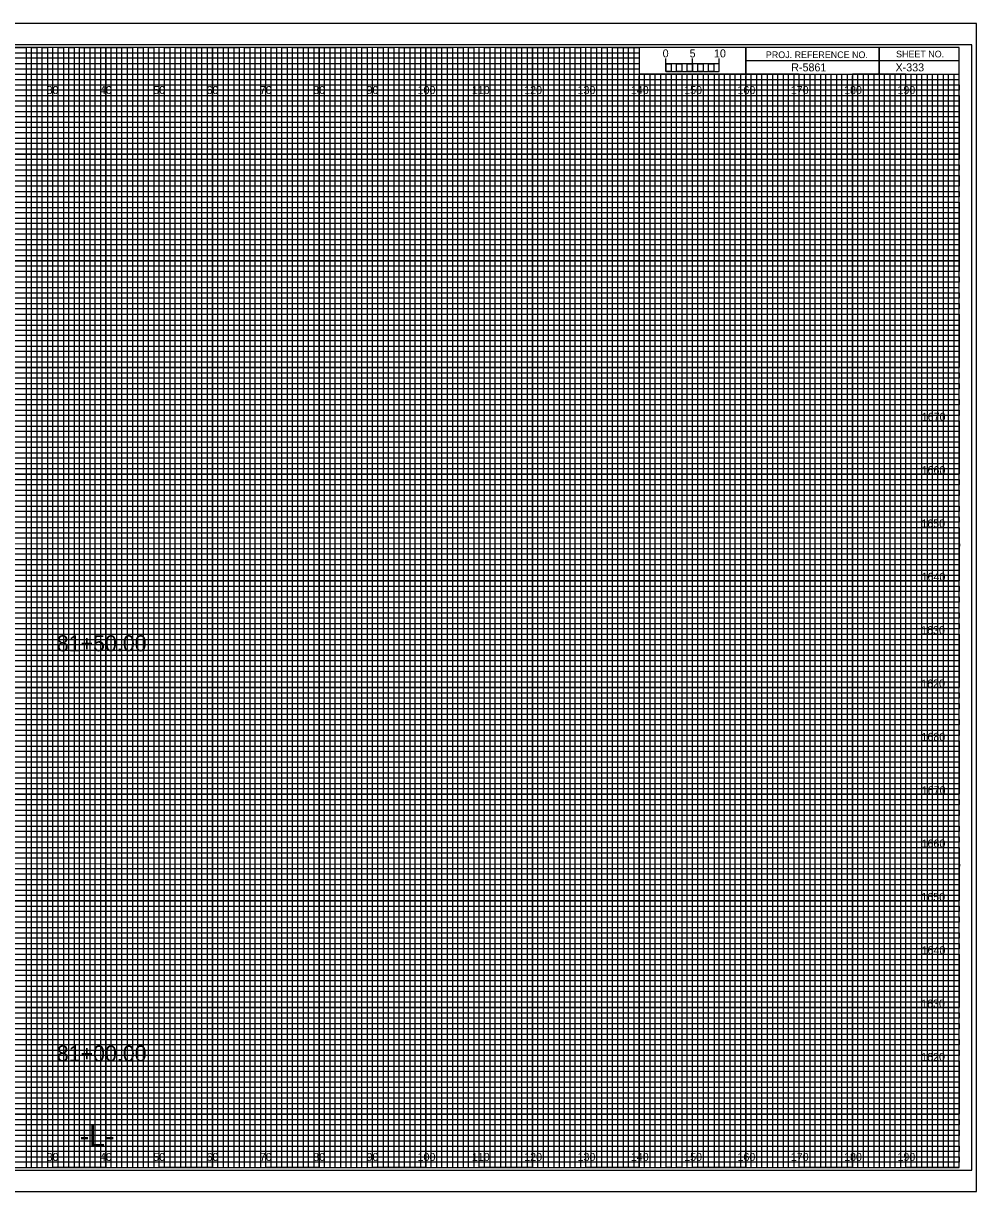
# Model space of a CAD drawing. Extents: x -13 to 1780, y -15 to 3284.
# Drawn here: x 144.5 to 323.3, y 215.5 to 434.5 of the extents above; entities that cross this region are included whole.
import ezdxf

# ---------------------------------------------------------------- set-up
doc = ezdxf.new("R2010")
doc.units = 0
for name, color, linetype in [('Exist CMT Pavement', 7, 'Continuous'), ('Prop Horizontal Alignment', 7, 'Continuous'), ('Prop Retaining Wall', 7, 'Continuous'), ('Prop SS Cut Line', 7, 'Continuous'), ('Prop SS Fill Line', 7, 'Continuous'), ('Prop SS Transition Line', 7, 'Continuous'), ('Prop XS Bar Scale Labels', 7, 'Continuous'), ('Prop XS DDE', 7, 'Continuous'), ('Prop XS Earthwork Shape', 7, 'Continuous'), ('Prop XS Noise Wall', 7, 'Continuous'), ('Prop XS Retaining Wall', 7, 'Continuous'), ('Prop XS Station Labels', 7, 'Continuous'), ('Raster_Level_0', 7, 'Continuous'), ('Scratch_Level_3', 7, 'Continuous'), ('Scratch_Level_7', 7, 'Continuous'), ('Typical Bridge Rail CELL', 7, 'Continuous'), ('Typical Median Barrier CELL', 7, 'Continuous')]:
    doc.layers.add(name, color=color, linetype=linetype)

msp = doc.modelspace()

# ---------------------------------------------------------------- linework, layer by layer
at = {"layer": 'Prop Retaining Wall'}
for p, q in [((305, 430), (305, 425)), ((305, 425), (305, 430)), ((280, 427.5), (280, 425)), ((320, 427.49), (280, 427.49)), ((280, 425), (320, 425))]:
    msp.add_line(p, q, dxfattribs=at)
for points in [[(320, 430), (0, 430), (0, 220), (320, 220)], [(280, 430), (260, 430), (260, 425.03), (280, 425.03)], [(320, 430), (280, 430), (280, 425), (320, 425)]]:
    msp.add_lwpolyline(points, close=True, dxfattribs=at)
at = {"layer": 'Prop SS Cut Line'}
for points in [[(135, 430), (145, 430), (145, 220), (155, 220), (155, 430), (165, 430), (165, 220), (175, 220), (175, 430), (185, 430), (185, 220), (195, 220), (195, 430), (205, 430), (205, 220), (215, 220), (215, 430), (225, 430), (225, 220), (235, 220), (235, 430), (245, 430), (245, 220), (255, 220), (255, 430), (259.93, 430), (260, 430), (260, 425), (264.99, 425), (264.99, 220), (275, 220), (275, 425), (285, 425), (285, 220), (295, 220), (295, 425), (305, 425), (305, 220), (315, 220), (315, 425)], [(0, 425), (275, 425)], [(0, 405), (320, 405), (320, 415), (0, 415)], [(0, 385), (320, 385), (320, 395), (0, 395)], [(0, 365), (320, 365), (320, 375), (0, 375)], [(0, 345), (320, 345), (320, 355), (0, 355)], [(0, 325), (320, 325), (320, 335), (0, 335)], [(0, 305), (320, 305), (320, 315), (0, 315)], [(0, 285), (320, 285), (320, 295), (0, 295)], [(0, 265), (320, 265), (320, 275), (0, 275)], [(0, 245), (320, 245), (320, 255), (0, 255)], [(0, 225), (320, 225), (320, 235), (0, 235)]]:
    msp.add_lwpolyline(points, dxfattribs=at)
at = {"layer": 'Prop SS Fill Line'}
for p, q in [((150, 430), (140, 430)), ((150, 220), (150, 430)), ((170, 430), (160, 430)), ((160, 430), (160, 220)), ((170, 220), (170, 430)), ((190, 430), (180, 430)), ((180, 430), (180, 220)), ((190, 220), (190, 430)), ((210, 430), (200, 430)), ((200, 430), (200, 220)), ((210, 220), (210, 430)), ((230, 430), (220, 430)), ((220, 430), (220, 220)), ((230, 220), (230, 430)), ((250, 430), (240, 430)), ((240, 430), (240, 220)), ((250, 220), (250, 430)), ((260, 430), (260, 220)), ((270, 220), (270, 425)), ((290, 425), (280, 425)), ((280, 425), (280, 220)), ((290, 220), (290, 425)), ((310, 425), (300, 425)), ((300, 425), (300, 220)), ((310, 220), (310, 425)), ((160, 220), (150, 220)), ((180, 220), (170, 220)), ((200, 220), (190, 220)), ((220, 220), (210, 220)), ((240, 220), (230, 220)), ((260, 220), (250, 220)), ((280, 220), (270, 220)), ((300, 220), (290, 220)), ((320, 220), (310, 220)), ((320, 220), (320, 220))]:
    msp.add_line(p, q, dxfattribs=at)
for points in [[(0, 420), (320, 420), (320, 410), (0, 410)], [(0, 400), (320, 400), (320, 390), (0, 390)], [(0, 380), (320, 380), (320, 370), (0, 370)], [(0, 360), (320, 360), (320, 350), (0, 350)], [(0, 340), (320, 340), (320, 330), (0, 330)], [(0, 320), (320, 320), (320, 310), (0, 310)], [(0, 300), (320, 300), (320, 290), (0, 290)], [(0, 280), (320, 280), (320, 270), (0, 270)], [(0, 260), (320, 260), (320, 250), (0, 250)], [(0, 240), (320, 240), (320, 230), (0, 230)]]:
    msp.add_lwpolyline(points, dxfattribs=at)
at = {"layer": 'Prop SS Transition Line'}
for p, q in [((0, 429), (260, 429)), ((260, 427.98), (0, 427.98)), ((260, 429), (260, 427.98)), ((0, 427), (260, 427)), ((260, 425.89), (0, 425.89)), ((260, 427), (260, 425.89)), ((0, 424), (320, 424))]:
    msp.add_line(p, q, dxfattribs=at)
for points in [[(0, 423), (270, 423), (320, 423), (320, 422), (0, 422)], [(0, 421), (320, 421), (320, 419), (0, 419)], [(0, 418), (320, 418), (320, 417), (0, 416.98)], [(0, 416), (320, 416), (320, 414), (0, 414)], [(0, 413), (320, 413), (320, 412), (0, 412)], [(0, 411), (320, 411), (320, 409), (0, 409)], [(0, 408), (320, 408), (320, 407), (0, 407)], [(0, 406), (320, 406), (320, 404), (0, 404)], [(0, 403), (320, 403), (320, 402), (0, 402)], [(0, 401), (320, 401), (320, 399), (0, 399)], [(0, 398), (320, 398), (320, 397), (0, 397)], [(0, 396), (320, 396), (320, 393.95), (320, 393), (320, 392), (0, 392)], [(0, 394), (320, 394), (320, 393), (0, 393)], [(0, 391), (320, 391), (320, 389), (0, 389.03)], [(0, 389.03), (320, 389), (320, 388), (0, 388)], [(0, 387), (320, 387), (320, 386), (0, 386)], [(0, 384), (320, 384), (320, 383), (0, 383)], [(0, 382), (320, 382), (320, 381), (0, 381)], [(-0.07, 378.89), (320, 378.89), (320, 377.88), (-0.07, 377.88)], [(0, 377), (320, 377), (320, 376), (0, 376)], [(0, 374), (320, 374), (320, 373), (0, 373)], [(0, 372), (320, 372), (320, 371), (0, 371)], [(0, 369), (320, 369), (320, 368), (0, 368)], [(0, 367), (320, 367), (320, 366), (0, 366)], [(0, 364), (320, 364), (320, 363), (0, 363)], [(0, 362), (320, 362), (320, 361), (0, 361)], [(0, 359), (320, 359), (319.99, 357.98), (0, 358)], [(0, 357), (320, 357), (320, 356), (0, 356)], [(0, 354), (320, 354), (320, 353), (0, 353)], [(0, 352), (320, 352), (320, 351), (0, 351)], [(0, 349), (320, 349), (320, 348), (0, 348)], [(0, 347), (320, 347), (320, 346), (0, 346)], [(0, 344), (320, 344), (320, 343), (0, 343)], [(0, 342), (320, 342), (320, 341), (0, 341)], [(0, 339), (320, 339), (320, 338), (0, 338)], [(0, 336.99), (320.07, 336.91), (320, 336), (0, 336)], [(0, 334), (320, 334), (320, 333), (0, 333)], [(0, 332), (320, 332), (320, 331), (0, 331)], [(0, 329), (320, 329), (320, 328), (0, 328)], [(0, 327), (320, 327), (320, 326), (0, 326)], [(0, 324), (320, 324), (320, 323), (0, 323)], [(0, 322), (320, 322), (320, 321), (0, 321)], [(0, 319), (320, 319), (320, 318), (0, 318)], [(0, 317), (320, 317), (320, 316), (0, 316)], [(0, 314), (320, 314), (320, 313), (0, 313)], [(0, 312), (320, 312), (320, 311), (0, 311)], [(0, 309), (320, 309), (320, 308), (0, 308)], [(0, 307), (320, 307), (320, 306), (0, 306)], [(0, 304), (320, 304), (320, 303), (0, 303)], [(0, 302), (320, 302), (320, 301), (0, 301)], [(0, 299), (320, 299), (319.99, 297.98), (0, 298)], [(0, 297), (320, 297), (320, 296), (0, 296)], [(0, 294), (320, 294), (320, 293), (0, 293)], [(0, 292), (320, 292), (320, 291), (0, 291)], [(0, 289), (320, 289), (320, 288), (0, 288)], [(0, 287), (320, 287), (320, 286), (0, 286)], [(0, 284), (320, 284), (320, 283), (0, 283)], [(0, 282), (320, 282), (320, 281), (0, 281)], [(0, 279), (320, 279), (320, 278), (0, 278)], [(0, 276.99), (320.07, 276.91), (320, 276), (0, 276)], [(0, 274), (320, 274), (320, 273), (0, 273)], [(0, 272), (320, 272), (320, 271), (0, 271)], [(0, 269), (320, 269), (320, 268), (0, 268)], [(0, 267), (320, 267), (320, 266), (0, 266)], [(0, 264), (320, 264), (320, 263), (0, 263)], [(0, 262), (320, 262), (320, 261), (0, 261)], [(0, 259), (320, 259), (320, 258), (0, 258)], [(0, 257), (320, 257), (320, 256), (0, 256)], [(0, 254), (320, 254), (320, 253), (0, 253)], [(0, 252), (320, 252), (320, 251), (0, 251)], [(0, 249), (320, 249), (320, 248), (0, 248)], [(0, 247), (320, 247), (320, 246), (0, 246)], [(0, 244), (320, 244), (320, 243), (0, 243)], [(0, 242), (320, 242), (320, 241), (0, 241)], [(0, 239), (320, 239), (320, 238), (0, 238)], [(0, 237), (320, 237), (320, 236), (0, 236)], [(0, 234), (320, 234), (320, 233), (0, 233)], [(0, 232), (320, 232), (320, 231), (0, 231)], [(0, 229), (320, 229), (320, 228), (0, 228)], [(0, 227), (320, 227), (320, 226), (0, 226)], [(0, 224), (320, 224), (320, 223), (0, 223)], [(0, 222), (320, 222), (320, 221), (0, 221)]]:
    msp.add_lwpolyline(points, dxfattribs=at)
at = {"layer": 'Prop XS Earthwork Shape'}
msp.add_lwpolyline([(-13.4, 215.5), (323.3, 215.5), (323.3, 434.5), (-13.4, 434.5)], close=True, dxfattribs=at)
at = {"layer": 'Prop XS Noise Wall'}
for p, q in [((150, 220), (150, 430)), ((160, 220), (160, 430)), ((170, 220), (170, 430)), ((180, 220), (180, 430)), ((190, 220), (190, 430)), ((200, 220), (200, 430)), ((210, 220), (210, 430)), ((220, 220), (220, 430)), ((230, 220), (230, 430)), ((240, 220), (240, 430)), ((250, 220), (250, 430)), ((260, 220), (260, 424.69)), ((270, 220), (270, 424.69)), ((280, 220), (280, 424.69)), ((290, 220), (290, 424.69)), ((300, 220), (300, 424.69)), ((310, 220), (310, 424.69)), ((0, 420), (320, 420)), ((0, 410), (320, 410)), ((0, 400), (320, 400)), ((0, 390), (320, 390)), ((0, 380), (320, 380)), ((0, 370), (320, 370)), ((0, 360), (320, 360)), ((0, 350), (320, 350)), ((0, 340), (320, 340)), ((0, 330), (320, 330)), ((0, 320), (320, 320)), ((0, 310), (320, 310)), ((0, 300), (320, 300)), ((0, 290), (320, 290)), ((0, 280), (320, 280)), ((0, 270), (320, 270)), ((0, 260), (320, 260)), ((0, 250), (320, 250)), ((0, 240), (320, 240)), ((0, 230), (320, 230))]:
    msp.add_line(p, q, dxfattribs=at)
at = {"layer": 'Prop XS Retaining Wall'}
for p, q in [((265, 425.49), (265, 427.9)), ((265, 426.9), (265, 427.9)), ((270, 425.49), (270, 427.9)), ((275, 425.49), (275, 427.9)), ((275, 426.9), (275, 427.9))]:
    msp.add_line(p, q, dxfattribs=at)
for points in [[(275, 426.9), (265, 426.9), (265, 425.49), (275, 425.49)], [(265, 426.9), (266, 426.9), (266, 425.49), (265, 425.49)], [(267, 426.9), (268, 426.9), (268, 425.49), (267, 425.49)], [(269, 426.9), (270, 426.9), (270, 425.49), (269, 425.49)], [(271, 426.9), (272, 426.9), (272, 425.49), (271, 425.49)], [(273, 426.9), (274, 426.9), (274, 425.49), (273, 425.49)]]:
    msp.add_lwpolyline(points, close=True, dxfattribs=at)
at = {"layer": 'Prop XS Station Labels'}
for p, q in [((323.3, 434.5), (-13.4, 434.5)), ((-13.4, 215.5), (323.3, 215.5))]:
    msp.add_line(p, q, dxfattribs=at)
at = {"layer": 'Scratch_Level_7'}
msp.add_lwpolyline([(-10.8, 219.5), (322.4, 219.5), (322.4, 430.5), (-10.8, 430.5)], close=True, dxfattribs=at)
at = {"layer": 'Typical Bridge Rail CELL'}
for p, q in [((267, 425), (266.01, 425)), ((266.01, 425), (266.01, 220)), ((267, 220), (267, 425)), ((269, 425), (268, 425)), ((268, 425), (268, 220)), ((269, 220), (269, 425)), ((266.01, 220), (265, 220)), ((268, 220), (267, 220))]:
    msp.add_line(p, q, dxfattribs=at)
for points in [[(145, 220), (146, 220), (146, 430), (147, 430), (147, 220)], [(147, 220), (148, 220), (148, 430), (149, 430), (149, 220)], [(150, 220), (151, 220), (151, 430), (152, 430), (152, 220)], [(152, 220), (153, 220), (153, 430), (154, 430), (154, 220)], [(155, 220), (156, 220), (156, 430), (157, 430), (157, 220)], [(157, 220), (158, 220), (158, 430), (159, 430), (159, 220)], [(160, 220), (161, 220), (161, 430), (162, 430), (162, 220)], [(162, 220), (163, 220), (163, 430), (164, 430), (164, 220)], [(165, 220), (166, 220), (166, 430), (167, 430), (167, 220)], [(167, 220), (168, 220), (168, 430), (169, 430), (169, 220)], [(170, 220), (171, 220), (171, 430), (172, 430), (172, 220)], [(172, 220), (173, 220), (173, 430), (174, 430), (174, 220)], [(175, 220), (176, 220), (176, 430), (177, 430), (177, 220)], [(177, 220), (178, 220), (178, 430), (179, 430), (179, 220)], [(180, 220), (181, 220), (181, 430), (182, 430), (182, 220)], [(182, 220), (183, 220), (183, 430), (184, 430), (184, 220)], [(185, 220), (186, 220), (186, 430), (187, 430), (187, 220)], [(187, 220), (188, 220), (188, 430), (189, 430), (189, 220)], [(190, 220), (191, 220), (191, 430), (192, 430), (192, 220)], [(192, 220), (193, 220), (193, 430), (194, 430), (194, 220)], [(195, 220), (196, 220), (196, 430), (197, 430), (197, 220)], [(197, 220), (198, 220), (198, 430), (199, 430), (199, 220)], [(200, 220), (201, 220), (201, 430), (202, 430), (202, 220)], [(202, 220), (203, 220), (203, 430), (204, 430), (204, 220)], [(205, 220), (206, 220), (206, 430), (207, 430), (207, 220)], [(207, 220), (208, 220), (208, 430), (209, 430), (209, 220)], [(210, 220), (211, 220), (211, 430), (212, 430), (212, 220)], [(212, 220), (213, 220), (213, 430), (214, 430), (214, 220)], [(215, 220), (216, 220), (216, 430), (217, 430), (217, 220)], [(217, 220), (218, 220), (218, 430), (219, 430), (219, 220)], [(220, 220), (221, 220), (221, 430), (222, 430), (222, 220)], [(222, 220), (223, 220), (223, 430), (224, 430), (224, 220)], [(225, 220), (226, 220), (226, 430), (227, 430), (227, 220)], [(227, 220), (228, 220), (228, 430), (229, 430), (229, 220)], [(230, 220), (231, 220), (231, 430), (232, 430), (232, 220)], [(232, 220), (233, 220), (233, 430), (234, 430), (234, 220)], [(235, 220), (236, 220), (236, 430), (237, 430), (237, 220)], [(237, 220), (238, 220), (238, 430), (239, 430), (239, 220)], [(240, 220), (241, 220), (241, 430), (242, 430), (242, 220)], [(242, 220), (243, 220), (243, 430), (244, 430), (244, 220)], [(245, 220), (246, 220), (246, 430), (247, 430), (247, 220)], [(247, 220), (248, 220), (248, 430), (249, 430), (249, 220)], [(250, 220), (251, 220), (251, 430), (252, 430), (252, 220)], [(252, 220), (253, 220), (253, 430), (254, 430), (254, 220)], [(255, 220), (256, 220), (256, 430), (257, 430), (257, 220)], [(257, 220), (258, 220), (258, 430), (259, 430), (259, 220)], [(260, 220), (261, 220), (261, 425), (262.02, 425), (262.02, 220)], [(262, 220), (263, 220), (263, 425), (263.99, 425), (263.99, 220)], [(270, 220), (270.98, 220), (270.98, 425), (272, 425), (272, 220)], [(272, 220), (273, 220), (273, 425), (274.05, 425), (274.05, 220)], [(275, 220), (276, 220), (276, 425), (277, 425), (277, 220)], [(277, 220), (278, 220), (278, 425), (279, 425), (279, 220)], [(280, 220), (281, 220), (281, 425), (282, 425), (282, 220)], [(282, 220), (283, 220), (283, 425), (284, 425), (284, 220)], [(285, 220), (286, 220), (286, 425), (287, 425), (287, 220)], [(287, 220), (288, 220), (288, 425), (289, 425), (289, 220)], [(290, 220), (291, 220), (291, 425), (292, 425), (292, 220)], [(292, 220), (293, 220), (293, 425), (294, 425), (294, 220)], [(295, 220), (296, 220), (296, 425), (297, 425), (297, 220)], [(297, 220), (298, 220), (298, 425), (299, 425), (299, 220)], [(300, 220), (301, 220), (301, 425), (302, 425), (302, 220)], [(302, 220), (303, 220), (303, 425), (304, 425), (304, 220)], [(305, 220), (306, 220), (306, 425), (307, 425), (307, 220)], [(307, 220), (308, 220), (308, 425), (309, 425), (309, 220)], [(310, 220), (311, 220), (311, 425), (312, 425), (312, 220)], [(312, 220), (313, 220), (313, 425), (314, 425), (314, 220)], [(315, 220), (316, 220), (316, 425), (317, 425), (317, 220)], [(317, 220), (318, 220), (318, 425), (319, 425), (319, 220)]]:
    msp.add_lwpolyline(points, dxfattribs=at)

# ---------------------------------------------------------------- texts
at = {"layer": 'Exist CMT Pavement'}
msp.add_text('R-5861', height=1.5, dxfattribs=at).set_placement((288.53, 425.5))
at = {"layer": 'Prop Horizontal Alignment'}
for s, p in [('81+50.00', (150.77, 316.79)), ('81+00.00', (150.77, 239.9))]:
    msp.add_text(s, height=3, dxfattribs=at).set_placement(p)
at = {"layer": 'Prop Retaining Wall'}
for s, p in [('PROJ. REFERENCE NO.', (283.77, 427.99)), ('SHEET NO.', (308.19, 428.12))]:
    msp.add_text(s, height=1.25, dxfattribs=at).set_placement(p)
at = {"layer": 'Prop XS Bar Scale Labels'}
for s, p in [('5', (269.47, 428.12)), ('10', (274.04, 428.12))]:
    msp.add_text(s, height=1.5, dxfattribs=at).set_placement(p)
at = {"layer": 'Prop XS DDE'}
msp.add_text('-L-', height=4, dxfattribs=at).set_placement((155.06, 224))
at = {"layer": 'Prop XS Retaining Wall'}
msp.add_text('0', height=1.5, dxfattribs=at).set_placement((264.41, 428.12))
at = {"layer": 'Raster_Level_0'}
for s, p in [('30', (148.86, 421.25)), ('40', (158.86, 421.25)), ('50', (168.86, 421.25)), ('60', (178.86, 421.25)), ('70', (188.86, 421.25)), ('80', (198.86, 421.25)), ('90', (208.86, 421.25)), ('100', (218.44, 421.25)), ('110', (228.62, 421.25)), ('120', (238.44, 421.25)), ('130', (248.44, 421.25)), ('140', (258.44, 421.25)), ('150', (268.44, 421.25)), ('160', (278.44, 421.25)), ('170', (288.44, 421.25)), ('180', (298.44, 421.25)), ('190', (308.44, 421.25)), ('30', (148.86, 221.25)), ('40', (158.86, 221.25)), ('50', (168.86, 221.25)), ('60', (178.86, 221.25)), ('70', (188.86, 221.25)), ('80', (198.86, 221.25)), ('90', (208.86, 221.25)), ('100', (218.44, 221.25)), ('110', (228.62, 221.25)), ('120', (238.44, 221.25)), ('130', (248.44, 221.25)), ('140', (258.44, 221.25)), ('150', (268.44, 221.25)), ('160', (278.44, 221.25)), ('170', (288.44, 221.25)), ('180', (298.44, 221.25)), ('190', (308.44, 221.25))]:
    msp.add_text(s, height=1.5, dxfattribs=at).set_placement(p)
at = {"layer": 'Scratch_Level_3'}
for s, p in [('1670', (313, 360)), ('1660', (312.97, 350)), ('1650', (312.92, 340)), ('1640', (312.97, 330)), ('1630', (312.89, 320)), ('1620', (312.9, 310)), ('1680', (312.95, 300)), ('1670', (313, 290)), ('1660', (312.97, 280)), ('1650', (312.92, 270)), ('1640', (312.97, 260)), ('1630', (312.89, 250)), ('1620', (312.9, 240))]:
    msp.add_text(s, height=1.5, dxfattribs=at).set_placement(p)
at = {"layer": 'Typical Median Barrier CELL'}
msp.add_text('X-333', height=1.5, dxfattribs=at).set_placement((308.09, 425.5))

doc.saveas('drawing.dxf')
